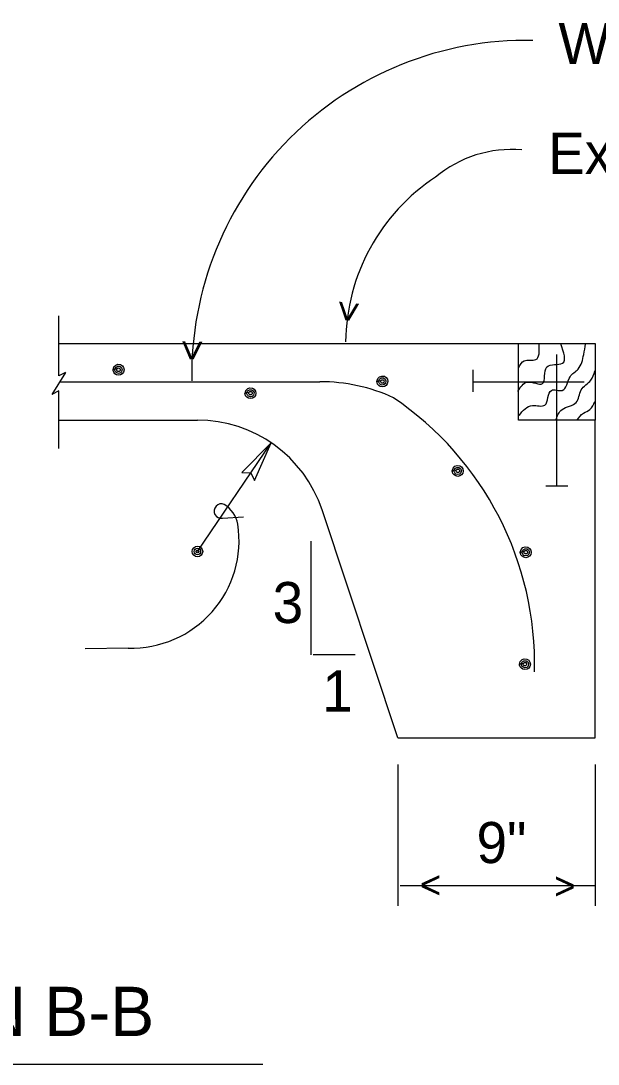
# Model space of a CAD drawing. Extents: x 0 to 3.31, y -0.03 to 1.83.
# Drawn here: x 1.5998 to 1.7829, y 0.5293 to 0.8601 of the extents above; entities that cross this region are included whole.
import ezdxf

# ---------------------------------------------------------------- set-up
doc = ezdxf.new("R2010")
doc.units = 0
for name, color, linetype in [('50', 7, 'Continuous'), ('51', 7, 'Continuous'), ('54', 7, 'Continuous'), ('55', 7, 'Continuous'), ('57', 7, 'Continuous')]:
    doc.layers.add(name, color=color, linetype=linetype)

msp = doc.modelspace()

# ---------------------------------------------------------------- linework, layer by layer
at = {"layer": '50'}
for p, q in [((1.611814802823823, 0.7578527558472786), (1.7575981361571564, 0.7578527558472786)), ((1.612189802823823, 0.7457027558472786), (1.6946564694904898, 0.7457027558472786)), ((1.611814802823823, 0.7335527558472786), (1.6557998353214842, 0.7335527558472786)), ((1.7818981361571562, 0.6328527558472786), (1.7818981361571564, 0.7335527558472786))]:
    msp.add_line(p, q, dxfattribs=at)
msp.add_lwpolyline([(1.7575981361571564, 0.7335527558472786), (1.7575981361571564, 0.7578527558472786), (1.7818981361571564, 0.7578527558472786), (1.7818981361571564, 0.7335527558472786)], close=True, dxfattribs=at)
at = {"layer": '51'}
for p, q in [((1.7697481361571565, 0.7127194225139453), (1.7697481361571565, 0.754386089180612)), ((1.630789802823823, 0.749536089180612), (1.630789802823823, 0.749536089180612)), ((1.630789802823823, 0.749536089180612), (1.630789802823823, 0.749536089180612)), ((1.7432648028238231, 0.7425110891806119), (1.7432648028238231, 0.7494527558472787)), ((1.7144481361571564, 0.745811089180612), (1.7144481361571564, 0.745811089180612)), ((1.7144481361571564, 0.745811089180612), (1.7144481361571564, 0.745811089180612)), ((1.7432648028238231, 0.7457027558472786), (1.7784314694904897, 0.7457027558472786)), ((1.672614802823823, 0.7420944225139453), (1.672614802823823, 0.7420944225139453)), ((1.672614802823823, 0.7420944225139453), (1.672614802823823, 0.7420944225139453)), ((1.7383564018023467, 0.7174451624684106), (1.7383564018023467, 0.7174451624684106)), ((1.7383564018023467, 0.7174451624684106), (1.7383564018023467, 0.7174451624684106)), ((1.7662731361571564, 0.7127194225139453), (1.7732231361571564, 0.7127194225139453)), ((1.7599185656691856, 0.6916440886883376), (1.7599185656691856, 0.6916440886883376)), ((1.7599185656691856, 0.6916440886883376), (1.7599185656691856, 0.6916440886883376)), ((1.7596615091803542, 0.6561702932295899), (1.7596615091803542, 0.6561702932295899)), ((1.7596615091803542, 0.6561702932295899), (1.7596615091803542, 0.6561702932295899))]:
    msp.add_line(p, q, dxfattribs=at)
for points in [[(1.6290564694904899, 0.7495444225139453), (1.6293064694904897, 0.7504194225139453), (1.6299064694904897, 0.751011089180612), (1.6305814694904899, 0.7512527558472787), (1.6314148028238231, 0.7511527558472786), (1.6320064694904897, 0.7507777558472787), (1.6323814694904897, 0.7502194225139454), (1.632514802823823, 0.7494944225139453), (1.6323564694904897, 0.748786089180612), (1.6319648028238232, 0.748261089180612), (1.6314564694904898, 0.7479360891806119), (1.6308064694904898, 0.7478027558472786), (1.6301314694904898, 0.7479360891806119), (1.629639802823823, 0.7482527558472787), (1.6292564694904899, 0.7487277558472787), (1.6290981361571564, 0.7491777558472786), (1.6290564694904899, 0.749486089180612), (1.6296564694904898, 0.749736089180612), (1.6298814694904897, 0.750261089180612), (1.6304481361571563, 0.750636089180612), (1.6311231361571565, 0.750636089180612), (1.6316564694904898, 0.7503027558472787), (1.631939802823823, 0.7497027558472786), (1.6317731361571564, 0.7489277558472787), (1.631364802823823, 0.7485277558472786), (1.630764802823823, 0.7483777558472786), (1.6302064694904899, 0.748536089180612), (1.629839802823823, 0.7488777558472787), (1.629639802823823, 0.7493194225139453), (1.629639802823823, 0.7497194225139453), (1.6303231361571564, 0.7498694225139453), (1.6306314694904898, 0.7500777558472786), (1.6310231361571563, 0.7500527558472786), (1.6313064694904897, 0.7497694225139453), (1.6312981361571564, 0.7492777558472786), (1.6309981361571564, 0.7489944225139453), (1.6305814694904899, 0.749011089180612), (1.6302648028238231, 0.7493027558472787), (1.6302231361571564, 0.749661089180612), (1.6303064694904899, 0.7498694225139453)], [(1.712714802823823, 0.7458194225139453), (1.7129648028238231, 0.7467027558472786), (1.713564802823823, 0.7472944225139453), (1.714239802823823, 0.747536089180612), (1.7150731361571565, 0.747436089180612), (1.715664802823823, 0.7470527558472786), (1.716039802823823, 0.7464944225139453), (1.7161731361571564, 0.7457777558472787), (1.7160148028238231, 0.7450694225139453), (1.7156231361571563, 0.7445444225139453), (1.715114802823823, 0.7442194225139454), (1.7144648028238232, 0.7440777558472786), (1.7137898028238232, 0.744211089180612), (1.7132981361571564, 0.744536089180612), (1.712914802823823, 0.7450027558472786), (1.7127564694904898, 0.7454527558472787), (1.712714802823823, 0.7457694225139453), (1.7133064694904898, 0.7460194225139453), (1.7135398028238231, 0.746536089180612), (1.7141064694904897, 0.746911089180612), (1.7147814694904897, 0.746911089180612), (1.7153148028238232, 0.746586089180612), (1.715589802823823, 0.7459860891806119), (1.7154314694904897, 0.745211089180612), (1.715014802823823, 0.7448027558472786), (1.7144231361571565, 0.744661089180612), (1.713864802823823, 0.744811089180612), (1.7134981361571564, 0.7451527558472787), (1.7132981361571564, 0.7456027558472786), (1.7132981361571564, 0.7460027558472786), (1.7139814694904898, 0.7461527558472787), (1.7142898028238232, 0.746361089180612), (1.7146814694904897, 0.746336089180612), (1.7149648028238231, 0.7460527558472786), (1.7149564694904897, 0.7455610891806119), (1.7146564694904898, 0.7452777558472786), (1.714239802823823, 0.745286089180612), (1.7139231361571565, 0.7455777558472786), (1.7138814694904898, 0.7459444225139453), (1.713964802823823, 0.7461527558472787)], [(1.670889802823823, 0.7421027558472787), (1.6711314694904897, 0.7429777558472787), (1.6717314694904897, 0.7435694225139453), (1.672414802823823, 0.743811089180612), (1.6732398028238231, 0.743711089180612), (1.6738314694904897, 0.7433277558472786), (1.674214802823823, 0.7427777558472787), (1.6743481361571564, 0.7420527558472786), (1.6741814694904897, 0.7413444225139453), (1.6737981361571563, 0.7408194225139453), (1.673289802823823, 0.7404944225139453), (1.6726314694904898, 0.7403610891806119), (1.6719564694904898, 0.7404944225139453), (1.6714731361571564, 0.740811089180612), (1.6710814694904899, 0.7412777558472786), (1.6709231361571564, 0.741736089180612), (1.6708814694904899, 0.7420444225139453), (1.6714814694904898, 0.7422944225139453), (1.6717148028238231, 0.742811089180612), (1.6722731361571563, 0.7431944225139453), (1.6729564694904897, 0.7431944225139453), (1.6734898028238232, 0.742861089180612), (1.673764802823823, 0.742261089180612), (1.6735981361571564, 0.741486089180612), (1.673189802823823, 0.7410860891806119), (1.6725981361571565, 0.7409360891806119), (1.672039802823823, 0.7410944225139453), (1.6716731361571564, 0.7414277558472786), (1.6714731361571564, 0.7418777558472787), (1.6714731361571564, 0.7422777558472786), (1.6721481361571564, 0.7424277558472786), (1.6724564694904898, 0.742636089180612), (1.6728481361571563, 0.742611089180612), (1.6731314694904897, 0.7423277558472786), (1.6731231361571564, 0.741836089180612), (1.6728314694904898, 0.7415527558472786), (1.6724064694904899, 0.7415610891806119), (1.6720898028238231, 0.741861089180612), (1.6720564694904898, 0.7422194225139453), (1.6721314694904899, 0.7424277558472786)], [(1.7366230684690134, 0.717453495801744), (1.7368730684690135, 0.718328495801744), (1.7374730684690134, 0.718928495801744), (1.7381480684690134, 0.7191618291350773), (1.7389814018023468, 0.7190618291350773), (1.7395730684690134, 0.7186868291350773), (1.7399480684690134, 0.718128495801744), (1.7400814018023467, 0.7174118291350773), (1.7399230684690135, 0.716703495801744), (1.7395314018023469, 0.7161701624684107), (1.7390230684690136, 0.7158451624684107), (1.7383730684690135, 0.7157118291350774), (1.7376980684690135, 0.7158451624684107), (1.7372064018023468, 0.7161618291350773), (1.7368230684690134, 0.7166368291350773), (1.73666473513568, 0.7170868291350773), (1.7366230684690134, 0.7173951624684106), (1.7372230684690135, 0.7176451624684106), (1.7374480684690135, 0.7181701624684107), (1.73801473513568, 0.7185451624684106), (1.73868973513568, 0.7185451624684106), (1.7392230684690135, 0.7182201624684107), (1.7395064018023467, 0.7176118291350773), (1.73933973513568, 0.7168368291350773), (1.7389314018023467, 0.7164368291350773), (1.7383314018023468, 0.7162951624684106), (1.7377730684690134, 0.7164451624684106), (1.7374064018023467, 0.7167868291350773), (1.7372064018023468, 0.717228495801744), (1.7372064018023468, 0.7176368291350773), (1.7378897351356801, 0.717778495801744), (1.7381980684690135, 0.7179951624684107), (1.73858973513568, 0.7179618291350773), (1.7388730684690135, 0.717678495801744), (1.73886473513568, 0.7171951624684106), (1.73856473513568, 0.716903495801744), (1.7381480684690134, 0.7169201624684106), (1.7378314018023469, 0.7172118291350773), (1.7377897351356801, 0.7175784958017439), (1.7378730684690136, 0.717778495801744)], [(1.7581852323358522, 0.6916524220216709), (1.7584352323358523, 0.692527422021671), (1.7590268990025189, 0.6931190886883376), (1.7597102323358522, 0.6933607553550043), (1.7605352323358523, 0.6932607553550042), (1.7611352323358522, 0.6928774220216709), (1.7615102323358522, 0.692327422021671), (1.7616435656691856, 0.6916024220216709), (1.7614852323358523, 0.6908940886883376), (1.7610935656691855, 0.6903690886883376), (1.7605852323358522, 0.6900440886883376), (1.759926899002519, 0.6899107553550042), (1.759251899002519, 0.6900440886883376), (1.7587685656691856, 0.6903607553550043), (1.7583852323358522, 0.6908274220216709), (1.758226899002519, 0.6912857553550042), (1.7581852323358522, 0.6915940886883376), (1.758776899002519, 0.6918440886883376), (1.7590102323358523, 0.6923607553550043), (1.7595685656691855, 0.6927440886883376), (1.7602518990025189, 0.6927440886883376), (1.7607852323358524, 0.6924107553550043), (1.7610602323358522, 0.6918107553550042), (1.760901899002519, 0.6910357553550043), (1.7604852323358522, 0.6906357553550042), (1.7598935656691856, 0.6904857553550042), (1.7593352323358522, 0.6906440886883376), (1.7589685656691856, 0.6909774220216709), (1.7587685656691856, 0.691427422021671), (1.7587685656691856, 0.6918274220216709), (1.7594435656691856, 0.6919774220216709), (1.7597602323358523, 0.6921857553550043), (1.760151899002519, 0.6921607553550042), (1.7604352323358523, 0.6918774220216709), (1.760426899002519, 0.6913857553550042), (1.760126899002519, 0.6911024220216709), (1.759701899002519, 0.6911107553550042), (1.7593935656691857, 0.6914107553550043), (1.759351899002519, 0.6917690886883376), (1.7594352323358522, 0.6919774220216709)], [(1.7579281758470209, 0.6561786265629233), (1.758178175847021, 0.6570536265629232), (1.7587698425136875, 0.6576452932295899), (1.7594531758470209, 0.6578869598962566), (1.760278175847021, 0.6577869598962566), (1.7608781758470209, 0.6574036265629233), (1.761253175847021, 0.6568536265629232), (1.7613865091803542, 0.6561286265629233), (1.761228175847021, 0.65542029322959), (1.7608365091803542, 0.65489529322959), (1.7603281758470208, 0.6545702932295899), (1.7596698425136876, 0.6544369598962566), (1.7589948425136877, 0.6545702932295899), (1.7585115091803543, 0.6548869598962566), (1.7581281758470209, 0.6553536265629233), (1.7579698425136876, 0.6558119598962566), (1.7579281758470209, 0.6561202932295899), (1.7585198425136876, 0.65637029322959), (1.758753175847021, 0.6568869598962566), (1.7593115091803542, 0.65727029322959), (1.7599948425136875, 0.65727029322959), (1.760528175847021, 0.6569369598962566), (1.7608031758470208, 0.6563369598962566), (1.7606448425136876, 0.6555619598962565), (1.7602281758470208, 0.6551619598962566), (1.7596365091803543, 0.6550119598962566), (1.7590781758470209, 0.6551702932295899), (1.7587115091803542, 0.6555036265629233), (1.7585115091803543, 0.6559536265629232), (1.7585115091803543, 0.6563536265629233), (1.7591865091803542, 0.6565036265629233), (1.759503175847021, 0.6567119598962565), (1.7598948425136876, 0.6566869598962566), (1.760178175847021, 0.6564036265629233), (1.7601698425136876, 0.6559119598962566), (1.7598698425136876, 0.6556286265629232), (1.7594448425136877, 0.6556369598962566), (1.7591365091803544, 0.6559369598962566), (1.7590948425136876, 0.6562952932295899), (1.7591781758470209, 0.6565036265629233)]]:
    msp.add_lwpolyline(points, dxfattribs=at)
for centre, radius, start, end in [((1.6950838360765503, 0.6913081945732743), 0.054396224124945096, 65.1398138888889, 90.44795555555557), ((1.6607587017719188, 0.6562569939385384), 0.10195895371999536, 358.55512831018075, 55.87866388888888)]:
    msp.add_arc(centre, radius, start, end, dxfattribs=at)
at = {"layer": '54'}
msp.add_lwpolyline([(1.6791405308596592, 0.7264016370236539), (1.669895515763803, 0.7169701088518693), (1.672707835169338, 0.7168891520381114), (1.6739350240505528, 0.7144195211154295)], close=True, dxfattribs=at)
at = {"layer": '55'}
for p, q in [((1.611814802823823, 0.7476194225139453), (1.611814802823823, 0.7666194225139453)), ((1.6139814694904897, 0.7486944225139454), (1.6096814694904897, 0.7417194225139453)), ((1.6139814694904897, 0.7486944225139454), (1.6118314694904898, 0.7476194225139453)), ((1.6118064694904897, 0.745236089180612), (1.6118064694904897, 0.745236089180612)), ((1.611814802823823, 0.742836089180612), (1.6096814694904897, 0.7417194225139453)), ((1.611814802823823, 0.7245078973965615), (1.611814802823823, 0.742836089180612)), ((1.6557998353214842, 0.691886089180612), (1.6791405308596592, 0.7264016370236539)), ((1.7193981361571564, 0.6328527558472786), (1.695328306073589, 0.7050622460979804)), ((1.663761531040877, 0.7024442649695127), (1.670436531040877, 0.7028525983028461)), ((1.6917949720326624, 0.695186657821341), (1.6917949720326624, 0.6591102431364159)), ((1.6338865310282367, 0.6612775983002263), (1.6201736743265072, 0.6610035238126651)), ((1.705811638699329, 0.6591102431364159), (1.6924783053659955, 0.6591102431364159)), ((1.7193981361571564, 0.6328527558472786), (1.7818981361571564, 0.6328527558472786)), ((1.7193981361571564, 0.624361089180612), (1.7193981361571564, 0.579561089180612)), ((1.7818981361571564, 0.624361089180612), (1.7818981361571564, 0.579561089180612)), ((1.7818981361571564, 0.5858860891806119), (1.7200564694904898, 0.5858860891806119))]:
    msp.add_line(p, q, dxfattribs=at)
for radius in [0.0016804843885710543, 0.001013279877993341, 0.0004194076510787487]:
    msp.add_circle((1.6557998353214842, 0.691886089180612), radius, dxfattribs=at)
for centre, radius, start, end in [((1.7601212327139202, 0.7478249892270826), 0.10614664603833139, 88.91935000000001, 180.97015555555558), ((1.75558085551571, 0.7814186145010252), 0.03796638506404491, 85.37045, 129.7445027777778), ((1.7662127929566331, 0.757652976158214), 0.06342722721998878, 123.39010833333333, 179.33774166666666), ((1.6557998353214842, 0.691886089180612), 0.04166666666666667, 18.434948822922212, 90.00000000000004), ((1.6633815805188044, 0.7047068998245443), 0.0023010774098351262, 66.38793055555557, 279.43154722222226), ((1.6591498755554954, 0.6986703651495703), 0.009646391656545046, 11.095894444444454, 57.64911666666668), ((1.6348643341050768, 0.6954055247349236), 0.03414193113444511, 268.3588611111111, 8.628258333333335)]:
    msp.add_arc(centre, radius, start, end, dxfattribs=at)
for points in [[(1.7574481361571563, 0.742636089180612), (1.7604314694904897, 0.7456194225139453), (1.7652064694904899, 0.7451444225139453), (1.766639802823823, 0.7503944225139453), (1.7715314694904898, 0.7515944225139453), (1.7710564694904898, 0.757736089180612)], [(1.757689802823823, 0.7502194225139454), (1.759414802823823, 0.7523694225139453), (1.7630564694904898, 0.7527277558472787), (1.7641314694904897, 0.757736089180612)], [(1.7578064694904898, 0.7349944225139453), (1.762039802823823, 0.7382194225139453), (1.7659814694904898, 0.738336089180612), (1.7680731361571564, 0.7429944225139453), (1.7714731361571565, 0.7429944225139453), (1.7739814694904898, 0.7472944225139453), (1.7764898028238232, 0.749736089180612), (1.7782814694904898, 0.754336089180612), (1.7788731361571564, 0.7576777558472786)], [(1.7694481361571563, 0.733561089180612), (1.771414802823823, 0.736911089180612), (1.7759481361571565, 0.7391777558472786), (1.7775064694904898, 0.743111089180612), (1.7805481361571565, 0.7462194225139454), (1.7817981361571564, 0.7491444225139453)], [(1.7761898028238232, 0.733561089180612), (1.7782148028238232, 0.7357694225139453), (1.7802481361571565, 0.736911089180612), (1.7818564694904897, 0.7394110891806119)]]:
    msp.add_spline(points, degree=3, dxfattribs=at)
at = {"layer": '57'}
msp.add_line((1.5045064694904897, 0.5293479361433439), (1.6765731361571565, 0.5293479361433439), dxfattribs=at)

# ---------------------------------------------------------------- texts
at = {"layer": '55'}
for height, rotation, p in [(0.008672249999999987, 264.0274916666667, (1.699839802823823, 0.7717777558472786)), (0.008672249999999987, 264.0274916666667, (1.699839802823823, 0.7717777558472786)), (0.008676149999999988, 268.3720055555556, (1.6500231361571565, 0.759161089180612))]:
    msp.add_text('>', height=height, rotation=rotation, dxfattribs=at).set_placement(p)
at = {"layer": '57'}
for s, height, p in [('Welded wire reinf.', 0.013016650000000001, (1.7702898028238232, 0.846436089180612)), ('Exposed Aggregate', 0.013016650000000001, (1.7670314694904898, 0.811636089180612)), ('3', 0.013016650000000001, (1.6796533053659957, 0.6692019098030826)), ('1', 0.013016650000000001, (1.695386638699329, 0.6411602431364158)), ('9"', 0.013016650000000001, (1.7442912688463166, 0.5931012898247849)), ('>', 0.008675, (1.7688814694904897, 0.5815527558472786)), ('>', 0.008675, (1.7688814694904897, 0.5815527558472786)), ('SECTION B-B', 0.015625, (1.5085898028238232, 0.5382562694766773))]:
    msp.add_text(s, height=height, dxfattribs=at).set_placement(p)
msp.add_text('>', height=0.008675, rotation=180, dxfattribs=at).set_placement((1.7330731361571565, 0.5902194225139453))
msp.add_text('>', height=0.008675, rotation=180, dxfattribs=at).set_placement((1.7330731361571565, 0.5902194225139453))

doc.saveas('drawing.dxf')
